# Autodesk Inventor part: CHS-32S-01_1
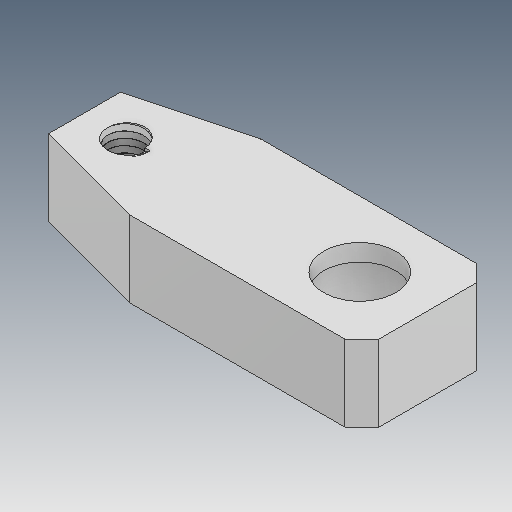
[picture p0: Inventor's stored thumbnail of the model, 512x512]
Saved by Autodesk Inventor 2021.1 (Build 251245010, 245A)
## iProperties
Created: 2021-05
Part Number: CHS-32S-01_1
Material: Ogólny
Document SubType Name: Modeling
Designer: user
Density: 1 g/cm^3
Appearance: Domyślna
Author: user
Revision Number: ÈÎºÎ
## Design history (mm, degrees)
feature "ÊäÈë1"
node "Bryła1"
